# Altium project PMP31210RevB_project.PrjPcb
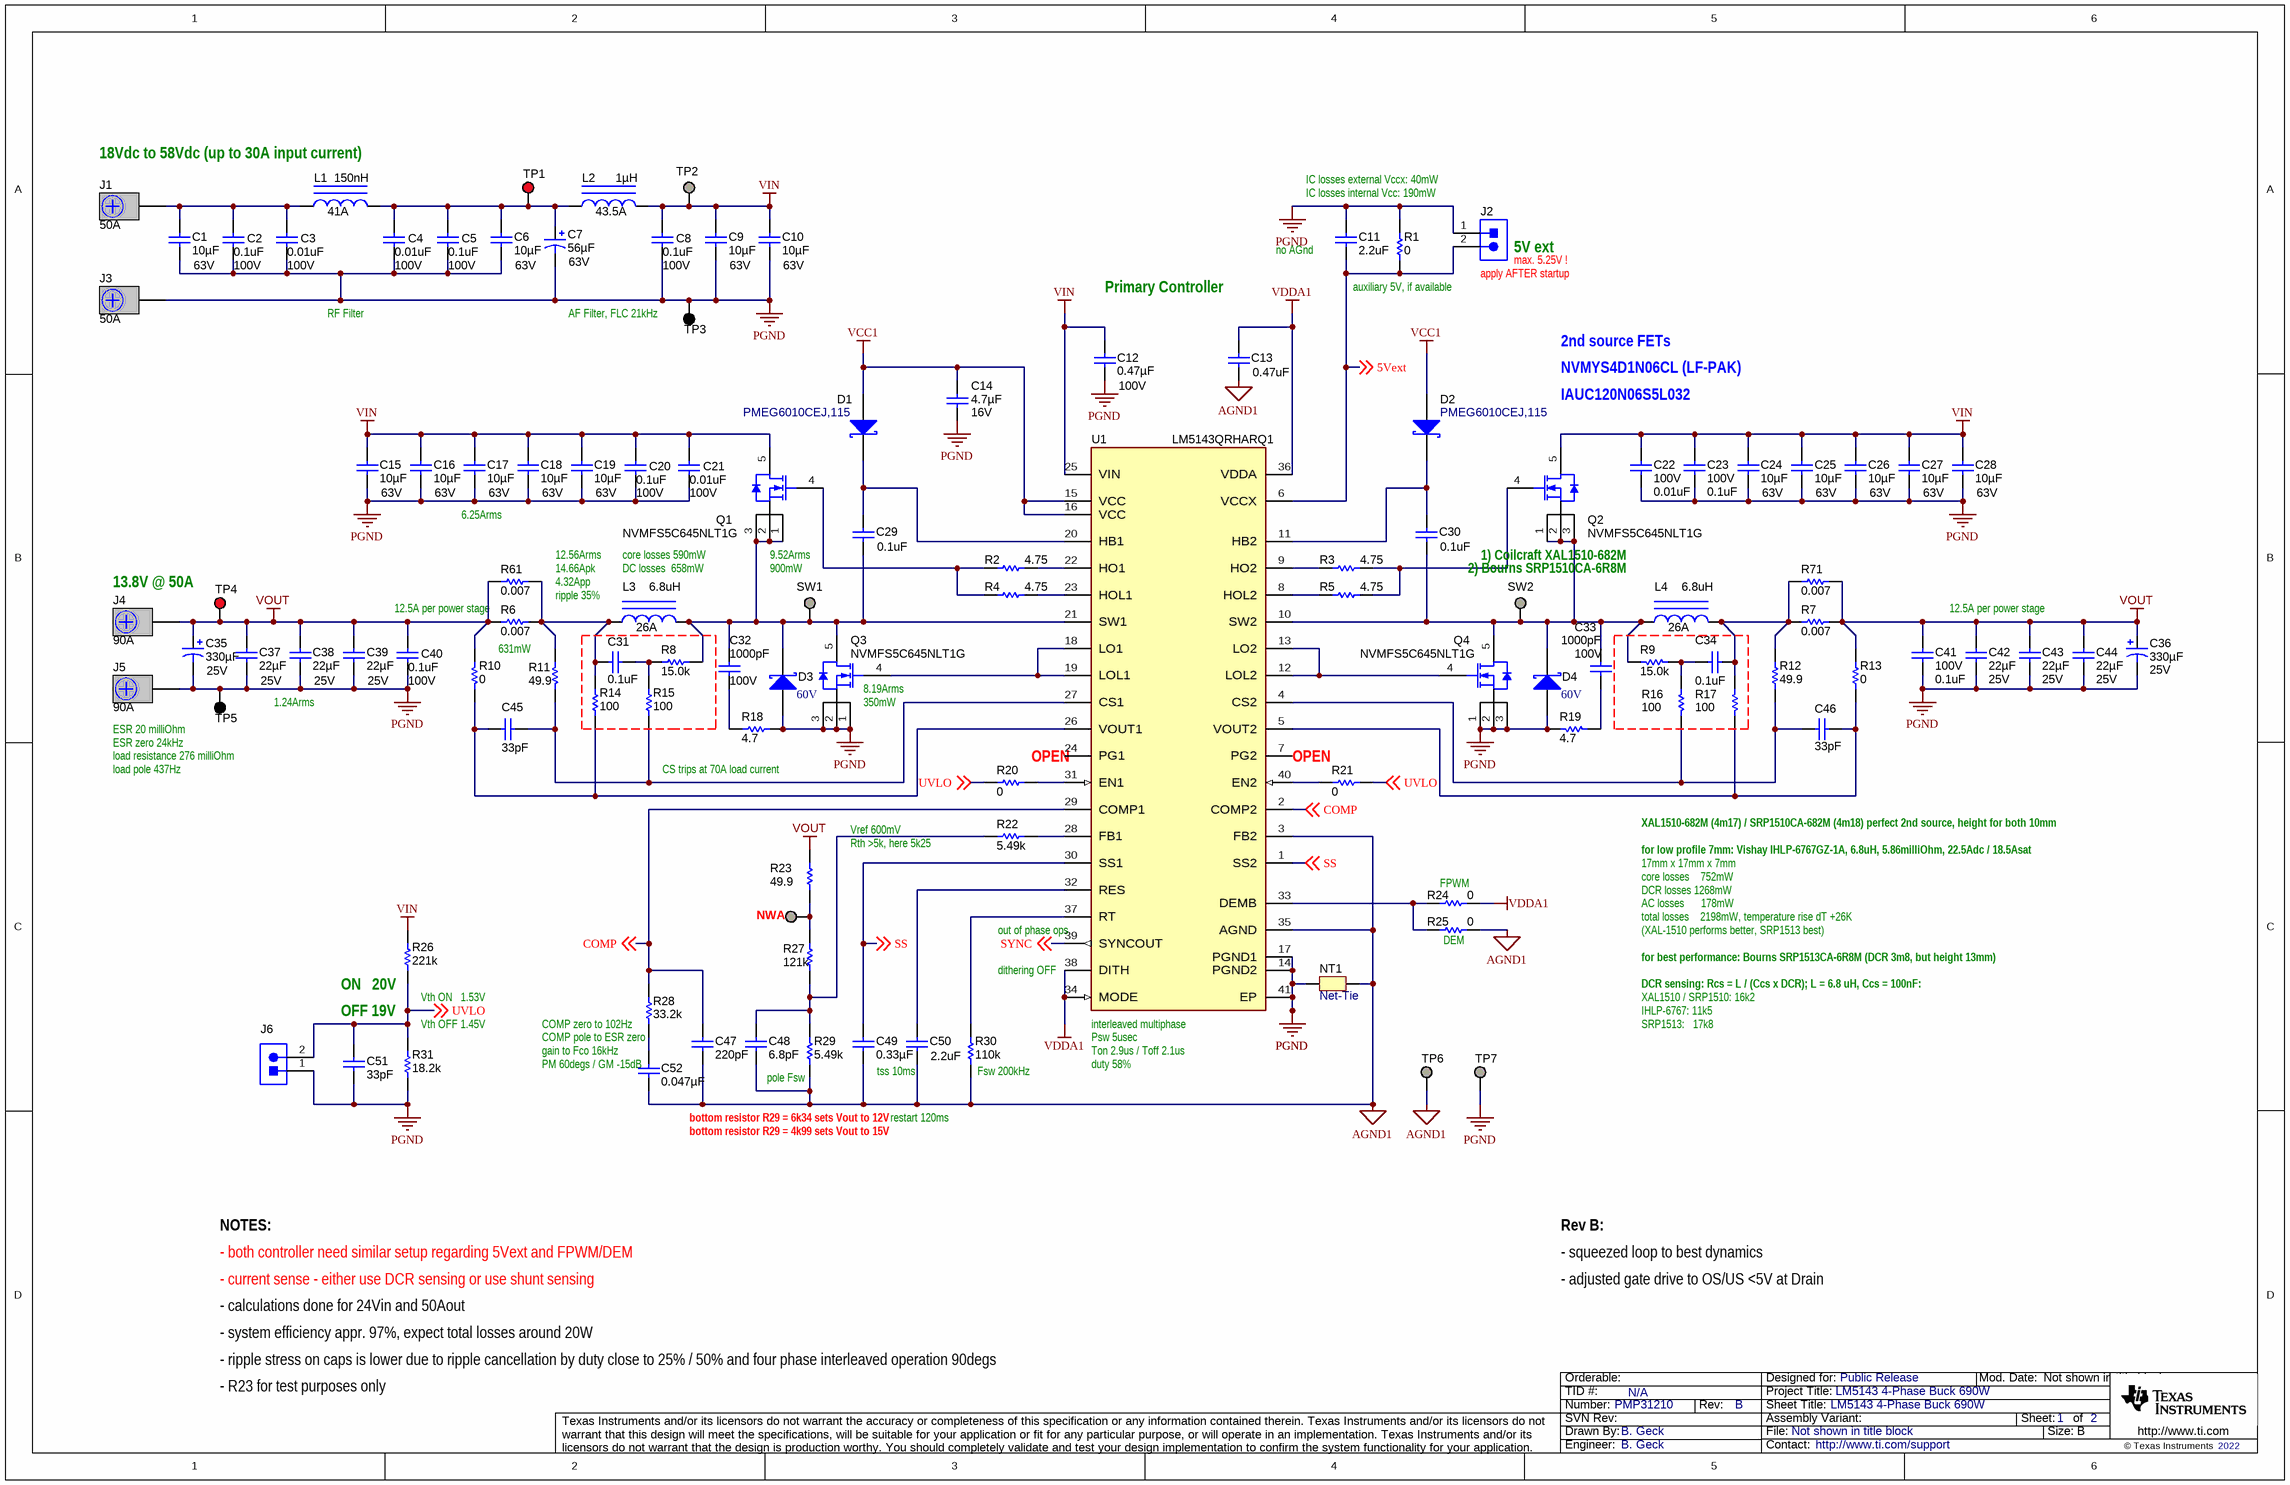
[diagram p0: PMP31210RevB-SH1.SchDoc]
CopyrightYear: 2022; PCB_Layout: B. Geck; PCB_Rev: A3; PRJ_Customer: Public Release; PRJ_Engineer: B. Geck; PRJ_Number: PMP31210; PRJ_Title: LM5143 4-Phase Buck 690W; SCH_Rev: B; TechSupport: http://www.ti.com/support; TID: N/A
2 sheets, 194 parts. Net scope: global (net labels, ports and power ports of the same name join across sheets).
Board file: PMP31202RevA3_board.PcbDoc
Sheets:
  PMP31210RevB-SH1.SchDoc
  PMP31210RevB-SH2.SchDoc

## Sheet PMP31210RevB-SH1.SchDoc: LM5143 4-Phase Buck 690W
size 431 x 279 mm; Date: Not shown in title block; ApprovedBy: Not shown in title block; CheckedBy: Not shown in title block; Author: Not shown in title block; CompanyName: Not shown in title block; DrawnBy: B. Geck; Engineer: Not shown in title block; Organization: Not shown in title block; Address1: Not shown in title block; Address2: Not shown in title block; Address3: Not shown in title block; Address4: Not shown in title block; DocumentNumber: 2; Revision: Use project parameter SCH_Rev; SheetNumber: 1; SheetTotal: 2; PageSetup: Record=PageOptions¦CenterHorizontal=True¦CenterVertical=True¦PrintScale=0.96¦XCorrection=1.00¦YCorrection=1.00¦PrintKind=0¦BorderSize=5000000¦LeftOffset=0¦BottomOffset=0¦Orientation=2¦PaperLength=1000¦PaperWidth=1000¦Scale=100¦PaperSource=7¦PrintQuality=600¦MediaType=1¦DitherType=10¦PaperKind=11" x 17"¦PrintScaleMode=1

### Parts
C1  ValueDisplayed: 10µF  Value2: 63V  [1210_270]  (hidden comment: GRM32ER71J106KA12L)
C2  VDC_V: 100V  ValueDisplayed: 0.1uF  [0805_HV]  (hidden comment: C0805C104K1RACTU)
C3  Value2: 100V  ValueDisplayed: 0.01uF  [0603L]  (hidden comment: GRM188R72A103KA01D)
C4  Value2: 100V  ValueDisplayed: 0.01uF  [0603L]  (hidden comment: GRM188R72A103KA01D)
C5  VDC_V: 100V  ValueDisplayed: 0.1uF  [0805_HV]  (hidden comment: C0805C104K1RACTU)
C6  ValueDisplayed: 10µF  Value2: 63V  [1210_270]  (hidden comment: GRM32ER71J106KA12L)
C7  ValueDisplayed: 56µF  Value2: 63V  [SM_RADIAL_10BMM]  (hidden comment: EEHZC1J560P)
C8  VDC_V: 100V  ValueDisplayed: 0.1uF  [0805_HV]  (hidden comment: C0805C104K1RACTU)
C9  ValueDisplayed: 10µF  Value2: 63V  [1210_270]  (hidden comment: GRM32ER71J106KA12L)
C10  ValueDisplayed: 10µF  Value2: 63V  [1210_270]  (hidden comment: GRM32ER71J106KA12L)
C11  ValueDisplayed: 2.2uF  [0603L]  (hidden comment: GRM188R71A225KE15D)
C12  ValueDisplayed: 0.47µF  Value2: 100V  [0805_HV]  (hidden comment: GRM21BR72A474KA73L)
C13  ValueDisplayed: 0.47uF  [0603L]  (hidden comment: GCM188R71C474KA55D)
C14  ValueDisplayed: 4.7µF  Value2: 16V  [0603]  (hidden comment: GRM188Z71C475KE21D)
C15  ValueDisplayed: 10µF  Value2: 63V  [1210_270]  (hidden comment: GRM32ER71J106KA12L)
C16  ValueDisplayed: 10µF  Value2: 63V  [1210_270]  (hidden comment: GRM32ER71J106KA12L)
C17  ValueDisplayed: 10µF  Value2: 63V  [1210_270]  (hidden comment: GRM32ER71J106KA12L)
C18  ValueDisplayed: 10µF  Value2: 63V  [1210_270]  (hidden comment: GRM32ER71J106KA12L)
C19  ValueDisplayed: 10µF  Value2: 63V  [1210_270]  (hidden comment: GRM32ER71J106KA12L)
C20  VDC_V: 100V  ValueDisplayed: 0.1uF  [0805_HV]  (hidden comment: C0805C104K1RACTU)
C21  Value2: 100V  ValueDisplayed: 0.01uF  [0603L]  (hidden comment: GRM188R72A103KA01D)
C22  Value2: 100V  ValueDisplayed: 0.01uF  [0603L]  (hidden comment: GRM188R72A103KA01D)
C23  VDC_V: 100V  ValueDisplayed: 0.1uF  [0805_HV]  (hidden comment: C0805C104K1RACTU)
C24  ValueDisplayed: 10µF  Value2: 63V  [1210_270]  (hidden comment: GRM32ER71J106KA12L)
C25  ValueDisplayed: 10µF  Value2: 63V  [1210_270]  (hidden comment: GRM32ER71J106KA12L)
C26  ValueDisplayed: 10µF  Value2: 63V  [1210_270]  (hidden comment: GRM32ER71J106KA12L)
C27  ValueDisplayed: 10µF  Value2: 63V  [1210_270]  (hidden comment: GRM32ER71J106KA12L)
C28  ValueDisplayed: 10µF  Value2: 63V  [1210_270]  (hidden comment: GRM32ER71J106KA12L)
C29  ValueDisplayed: 0.1uF  [0603L]  (hidden comment: CGA3E2X7R1E104K080AA)
C30  ValueDisplayed: 0.1uF  [0603L]  (hidden comment: CGA3E2X7R1E104K080AA)
C31  ValueDisplayed: 0.1uF  [0603L]  (hidden comment: CGA3E2X7R1E104K080AA)
C32  ValueDisplayed: 1000pF  Value2: 100V  [0603]  (hidden comment: GRM188R72A102KA01D)
C33  ValueDisplayed: 1000pF  Value2: 100V  [0603]  (hidden comment: GRM188R72A102KA01D)
C34  ValueDisplayed: 0.1uF  [0603L]  (hidden comment: CGA3E2X7R1E104K080AA)
C35  ValueDisplayed: 330µF  Value2: 25V  [SM_RADIAL_10BMM]  (hidden comment: EEHZC1E331P)
C36  ValueDisplayed: 330µF  Value2: 25V  [SM_RADIAL_10BMM]  (hidden comment: EEHZC1E331P)
C37  ValueDisplayed: 22µF  Value2: 25V  [1210_270]  (hidden comment: GRM32ER71E226KE15L)
C38  ValueDisplayed: 22µF  Value2: 25V  [1210_270]  (hidden comment: GRM32ER71E226KE15L)
C39  ValueDisplayed: 22µF  Value2: 25V  [1210_270]  (hidden comment: GRM32ER71E226KE15L)
C40  VDC_V: 100V  ValueDisplayed: 0.1uF  [0805_HV]  (hidden comment: C0805C104K1RACTU)
C41  VDC_V: 100V  ValueDisplayed: 0.1uF  [0805_HV]  (hidden comment: C0805C104K1RACTU)
C42  ValueDisplayed: 22µF  Value2: 25V  [1210_270]  (hidden comment: GRM32ER71E226KE15L)
C43  ValueDisplayed: 22µF  Value2: 25V  [1210_270]  (hidden comment: GRM32ER71E226KE15L)
C44  ValueDisplayed: 22µF  Value2: 25V  [1210_270]  (hidden comment: GRM32ER71E226KE15L)
C45  ValueDisplayed: 33pF  [0603L]  (hidden comment: 06031A330JAT2A)
C46  ValueDisplayed: 33pF  [0603L]  (hidden comment: 06031A330JAT2A)
C47  ValueDisplayed: 220pF  [0603]  (hidden comment: GRM188R71H221KA01D)
C48  ValueDisplayed: 6.8pF  [0603]  (hidden comment: 06035A6R8CAT2A)
C49  ValueDisplayed: 0.33µF  [0603]  (hidden comment: GRM188R71C334KA01D)
C50  ValueDisplayed: 2.2uF  [0603L]  (hidden comment: GRM188R71A225KE15D)
C51  ValueDisplayed: 33pF  [0603L]  (hidden comment: 06031A330JAT2A)
C52  ValueDisplayed: 0.047µF  [0603]  (hidden comment: GRM188R71C473KA01D)
D1  PMEG6010CEJ,115  [SOD-323F]
D2  PMEG6010CEJ,115  [SOD-323F]
D3  value 60V  [SMA]  (hidden comment: B360A-13-F)
D4  value 60V  [SMA]  (hidden comment: B360A-13-F)
J1  Current_A: 50A  [CB35-36-CY]  (hidden comment: CB35-36-CY)
J2  TSM-102-03-T-SV  [Samtec_TSM-102-03-x-SV]  (value not drawn)
J3  Current_A: 50A  [CB35-36-CY]  (hidden comment: CB35-36-CY)
J4  Current_A: 90A  [CB70-14-CY]  (hidden comment: CB70-14-CY)
J5  Current_A: 90A  [CB70-14-CY]  (hidden comment: CB70-14-CY)
J6  TSM-102-03-T-SV  [Samtec_TSM-102-03-x-SV]  (value not drawn)
L1  ValueDisplayed: 150nH  Value2: 41A  [PA2607NL]  (hidden comment: PA2607.151NLT)
L2  ValueDisplayed: 1µH  Value2: 43.5A  [XAL1010]  (hidden comment: XAL1010-102MEB)
L3  Imax_A: 26A  ValueDisplayed: 6.8uH  [XAL1510]  (hidden comment: XAL1510-682MEB)
L4  Imax_A: 26A  ValueDisplayed: 6.8uH  [XAL1510]  (hidden comment: XAL1510-682MEB)
NT1  Net-Tie  [Net-Tie_10mil]  (net tie, no BOM)
NWA  5019  [Keystone_5019]  (value not drawn)
Q1  NVMFS5C645NLT1G  [SO-8FL]
Q2  NVMFS5C645NLT1G  [SO-8FL]
Q3  NVMFS5C645NLT1G  [SO-8FL]
Q4  NVMFS5C645NLT1G  [SO-8FL]
R1  ValueDisplayed: 0  [0603]  (hidden comment: CRCW06030000Z0EA)
R2  ValueDisplayed: 4.75  [0603]  (hidden comment: CRCW06034R75FKEA)
R3  ValueDisplayed: 4.75  [0603]  (hidden comment: CRCW06034R75FKEA)
R4  ValueDisplayed: 4.75  [0603]  (hidden comment: CRCW06034R75FKEA)
R5  ValueDisplayed: 4.75  [0603]  (hidden comment: CRCW06034R75FKEA)
R6  ValueDisplayed: 0.007  [PE1206]  (hidden comment: PE1206FRF470R007L)
R7  ValueDisplayed: 0.007  [PE1206]  (hidden comment: PE1206FRF470R007L)
R8  ValueDisplayed: 15.0k  [0603]  (hidden comment: CRCW060315K0FKEA)
R9  ValueDisplayed: 15.0k  [0603]  (hidden comment: CRCW060315K0FKEA)
R10  ValueDisplayed: 0  [0603L]  (hidden comment: CRCW06030000Z0EA)
R11  ValueDisplayed: 49.9  [0603L]  (hidden comment: CRCW060349R9FKEA)
R12  ValueDisplayed: 49.9  [0603L]  (hidden comment: CRCW060349R9FKEA)
R13  ValueDisplayed: 0  [0603L]  (hidden comment: CRCW06030000Z0EA)
R14  ValueDisplayed: 100  [0603]  (hidden comment: CRCW0603100RFKEA)
R15  ValueDisplayed: 100  [0603]  (hidden comment: CRCW0603100RFKEA)
R16  ValueDisplayed: 100  [0603]  (hidden comment: CRCW0603100RFKEA)
R17  ValueDisplayed: 100  [0603]  (hidden comment: CRCW0603100RFKEA)
R18  ValueDisplayed: 4.7  [1206]  (hidden comment: CRCW12064R70JNEAHP)
R19  ValueDisplayed: 4.7  [1206]  (hidden comment: CRCW12064R70JNEAHP)
R20  ValueDisplayed: 0  [0603]  (hidden comment: CRCW06030000Z0EA)
R21  ValueDisplayed: 0  [0603]  (hidden comment: CRCW06030000Z0EA)
R22  ValueDisplayed: 5.49k  [0603]  (hidden comment: CRCW06035K49FKEA)
R23  ValueDisplayed: 49.9  [0603]  (hidden comment: CRCW060349R9FKEA)
R24  ValueDisplayed: 0  [0603]  (hidden comment: CRCW06030000Z0EA)
R25  ValueDisplayed: 0  [0603]  (hidden comment: CRCW06030000Z0EA)
R26  ValueDisplayed: 221k  [0603]  (hidden comment: CRCW0603221KFKEA)
R27  ValueDisplayed: 121k  [0603]  (hidden comment: CRCW0603121KFKEA)
R28  ValueDisplayed: 33.2k  [0603]  (hidden comment: CRCW060333K2FKEA)
R29  ValueDisplayed: 5.49k  [0603]  (hidden comment: CRCW06035K49FKEA)
R30  ValueDisplayed: 110k  [0603]  (hidden comment: CRCW0603110KFKEA)
R31  ValueDisplayed: 18.2k  [0603]  (hidden comment: CRCW060318K2FKEA)
R61  ValueDisplayed: 0.007  [PE1206]  (hidden comment: PE1206FRF470R007L)
R71  ValueDisplayed: 0.007  [PE1206]  (hidden comment: PE1206FRF470R007L)
SW1  5019  [Keystone_5019]  (value not drawn)
SW2  5019  [Keystone_5019]  (value not drawn)
TP1  5010  [Keystone5010]  (value not drawn)
TP2  5019  [Keystone_5019]  (value not drawn)
TP3  5011  [Keystone5011]  (value not drawn)
TP4  5010  [Keystone5010]  (value not drawn)
TP5  5011  [Keystone5011]  (value not drawn)
TP6  5019  [Keystone_5019]  (value not drawn)
TP7  5019  [Keystone_5019]  (value not drawn)
U1  LM5143QRHARQ1  [RHA0040N-MFG]

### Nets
AGND1: C13.1 C47.2 C48.2 C49.2 C50.2 C52.2 NT1.2 R25.2 R29.1 R30.1 TP6.1 U1.3(FB2) U1.35(AGND)
PGND: C1.2 C2.1 C3.1 C4.1 C5.1 C6.2 C7.2(-) C8.1 C9.2 C10.2 C11.2 C12.2 C14.2 C15.2 C16.2 C17.2 C18.2 C19.2 C20.1 C21.1 C22.1 C23.1 C24.2 C25.2 C26.2 C27.2 C28.2 C35.2(-) C36.2(-) C37.2 C38.2 C39.2 C40.1 C41.1 C42.2 C43.2 C44.2 C51.2 D3.2(A) D4.2(A) J2.1 J3.1 J5.1 J6.1 NT1.1 Q3.1(S) Q3.2(S) Q3.3(S) Q4.1(S) Q4.2(S) Q4.3(S) R1.1 R18.1 R19.2 R31.1 TP3.1 TP5.1 TP7.1 U1.14(PGND2) U1.17(PGND1) U1.41(EP)
VCC1: C14.1 D1.2(A) D2.2(A) U1.15(VCC) U1.16(VCC)
VDDA1: C13.2 R24.2 U1.34(MODE) U1.36(VDDA) U1.38(DITH)
VIN: C8.2 C9.1 C10.1 C12.1 C15.1 C16.1 C17.1 C18.1 C19.1 C20.2 C21.2 C22.2 C23.2 C24.1 C25.1 C26.1 C27.1 C28.1 L2.2 Q1.5(D) Q2.5(D) R26.2 TP2.1 U1.25(VIN)
VOUT: C35.1(+) C36.1(+) C37.1 C38.1 C39.1 C40.2 C41.2 C42.1 C43.1 C44.1 J4.1 R6.1 R7.2 R10.2 R13.2 R23.2 R61.1 R71.2 TP4.1
5Vext: C11.1 J2.2 R1.2 U1.6(VCCX) ; off-sheet 5Vext
COMP: C47.1 R28.2 U1.2(COMP2) U1.29(COMP1) ; off-sheet COMP
SS: C49.1 U1.1(SS2) U1.30(SS1) ; off-sheet SS
SYNC: U1.39(SYNCOUT) ; off-sheet SYNC
UVLO: C51.1 J6.2 R20.1 R21.2 R26.1 R31.2 ; off-sheet UVLO
NetC1_1: C1.1 C2.2 C3.2 J1.1 L1.1
NetC4_2: C4.2 C5.2 C6.1 C7.1(+) L1.2 L2.1 TP1.1
NetC29_1: C29.1 C32.1 D3.1(K) L3.2 Q1.1(S) Q1.2(S) Q1.3(S) Q3.5(D) R8.2 SW1.1 U1.21(SW1)
NetC29_2: C29.2 D1.1(K) U1.20(HB1)
NetC30_1: C30.1 C33.1 D4.1(K) L4.2 Q2.1(S) Q2.2(S) Q2.3(S) Q4.5(D) R9.2 SW2.1 U1.10(SW2)
NetC30_2: C30.2 D2.1(K) U1.11(HB2)
NetC31_1: C31.1 R8.1 R15.2
NetC31_2: C31.2 L3.1 R6.2 R11.2 R14.2 R61.2
NetC32_2: C32.2 R18.2
NetC33_2: C33.2 R19.1
NetC34_1: C34.1 R9.1 R16.2
NetC34_2: C34.2 L4.1 R7.1 R12.2 R17.2 R71.1
NetC45_1: C45.1 R10.1 R14.1 U1.26(VOUT1)
NetC45_2: C45.2 R11.1 R15.1 U1.27(CS1)
NetC46_1: C46.1 R13.1 R17.1 U1.5(VOUT2)
NetC46_2: C46.2 R12.1 R16.1 U1.4(CS2)
NetC48_1: C48.1 R22.1 R27.1 R29.2
NetC50_1: C50.1 U1.32(RES)
NetC52_1: C52.1 R28.1
NetNWA_1: NWA.1 R23.1 R27.2
NetQ1_4: Q1.4(G) R2.1 R4.1
NetQ2_4: Q2.4(G) R3.2 R5.2
NetQ3_4: Q3.4(G) U1.18(LO1) U1.19(LOL1)
NetQ4_4: Q4.4(G) U1.12(LOL2) U1.13(LO2)
NetR2_2: R2.2 U1.22(HO1)
NetR3_1: R3.1 U1.9(HO2)
NetR4_2: R4.2 U1.23(HOL1)
NetR5_1: R5.1 U1.8(HOL2)
NetR20_2: R20.2 U1.31(EN1)
NetR21_1: R21.1 U1.40(EN2)
NetR22_2: R22.2 U1.28(FB1)
NetR24_1: R24.1 R25.1 U1.33(DEMB)
NetR30_2: R30.2 U1.37(RT)

Not connected (* = marked no-connect by the designer): U1 7(PG2) 24(PG1)

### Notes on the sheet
- 18Vdc to 58Vdc (up to 30A input current)
- IC losses external Vccx: 40mW
- IC losses internal Vcc: 190mW
- Primary Controller
- (near C11) no AGnd
- auxiliary 5V, if available
- (near J2) apply AFTER startup
- (near J2) 5V ext
- (near J2) max. 5.25V !
- RF Filter
- (near TP3) AF Filter, FLC 21kHz
- 2nd source FETs
- NVMYS4D1N06CL (LF-PAK)
- IAUC120N06S5L032
- 6.25Arms
- (near R61) 12.56Arms
- (near R61) 14.66Apk
- core losses 590mW
- DC losses  658mW
- 9.52Arms
- 900mW
- (near R71) 1) Coilcraft XAL1510-682M
- (near R71) 2) Bourns SRP1510CA-6R8M
- 13.8V @ 50A
- (near R6) 12.5A per power stage
- 4.32App
- ripple 35%
- (near R7) 12.5A per power stage
- 1.24Arms
- 631mW
- (near Q3) 8.19Arms
- (near Q3) 350mW
- load resistance 276 milliOhm
- ESR 20 milliOhm
- ESR zero 24kHz
- load pole 437Hz
- CS trips at 70A load current
- OPEN
- (near R23) Vref 600mV
- Rth >5k, here 5k25
- XAL1510-682M (4m17) / SRP1510CA-682M (4m18) perfect 2nd source, height for both 10mm
- (near R24) FPWM
- for low profile 7mm: Vishay IHLP-6767GZ-1A, 6.8uH, 5.86milliOhm, 22.5Adc / 18.5Asat
- 17mm x 17mm x 7mm
- core losses    752mW
- DCR losses 1268mW
- AC losses      178mW
- (near U1) dithering OFF
- (near U1) out of phase ops
- (near R25) DEM
- total losses    2198mW, temperature rise dT +26K
- (XAL-1510 performs better, SRP1513 best)
- for best performance: Bourns SRP1513CA-6R8M (DCR 3m8, but height 13mm)
- (near R26) ON   20V
- OFF 19V
- (near R26) Vth ON   1.53V
- (near R31) Vth OFF 1.45V
- (near R28) COMP zero to 102Hz
- (near R28) COMP pole to ESR zero
- (near U1) interleaved multiphase
- (near U1) Psw 5usec
- DCR sensing: Rcs = L / (Ccs x DCR); L = 6.8 uH, Ccs = 100nF:
- XAL1510 / SRP1510: 16k2
- IHLP-6767: 11k5
- SRP1513:   17k8
- (near C52) gain to Fco 16kHz
- (near C52) PM 60degs / GM -15dB
- (near R29) pole Fsw
- tss 10ms
- (near R30) Fsw 200kHz
- (near U1) Ton 2.9us / Toff 2.1us
- duty 58%
- bottom resistor R29 = 6k34 sets Vout to 12V
- bottom resistor R29 = 4k99 sets Vout to 15V
- restart 120ms
- NOTES:
- Rev B:
- - calculations done for 24Vin and 50Aout
- - both controller need similar setup regarding 5Vext and FPWM/DEM
- - current sense - either use DCR sensing or use shunt sensing
- - squeezed loop to best dynamics
- - adjusted gate drive to OS/US <5V at Drain
- - ripple stress on caps is lower due to ripple cancellation by duty close to 25% / 50% and four phase interleaved operation 90degs
- - system efficiency appr. 97%, expect total losses around 20W
- - R23 for test purposes only

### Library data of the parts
C1 C6 C9 C10 C15-C19 C24-C28 = GRM32ER71J106KA12L: CAP, CERM, 10 µF, 63 V,+/- 10%, X7R, 1210; Manufacturer: MuRata; Polarized: N; CompType: Capacitor; Value: 10uF; U/M: EA; Cap_F: 0.00001; Tolerance_%: 10; VDC_V: 63; TaMin_C: -55; TaMax_C: 125; Cap_Case: 1210; SizeArea_mm2: 8; SizeAreaWB_mm2: 14.7; SizeX_mm: 3.2; SizeY_mm: 2.5; SizeZ_mm: 2.7; AEC Category: Q200; Green_Lifecycle: Active; Green_REACh: Passed
C2 C5 C8 C20 C23 C40 C41 = CMP-0007722-2: CAP, CERM, 0.1 uF, 100 V, +/- 10%, X7R, 0805; Manufacturer: Kemet; TaMin_C: -55°C; ESR_ohm: 0.064; Polarized: N; SizeAreaWB_mm2: 6.75; Value1: 0.064 ohm; U/M: EA; Value: 0.1uF; TaMax_C: 125°C; SizeZ_mm: 1.45; SizeX_mm: 2; SizeY_mm: 1.25; Cap_Case: 0805; SizeArea_mm2: 2.5; CompType: Capacitor; Cap_F: 100nF; IRMS_A: 1.64A; AEC Category: Q200
C3 C4 C21 C22 = CMP-0007468-5: CAP, CERM, 0.01 uF, 100 V, +/- 10%, X7R, 0603; Manufacturer: MuRata; TaMin_C: -55°C; Polarized: N; SizeAreaWB_mm2: 4.68; Value1: Unknown; U/M: EA; Value: 0.01uF; TaMax_C: 125°C; SizeZ_mm: 1; SizeX_mm: 1.6; SizeY_mm: 0.8; Cap_Case: 0603; SizeArea_mm2: 1.28; Cap_F: 10nF; AEC Category: Q200
C7 = EEHZC1J560P: CAP, Polymer Hybrid, 56 µF, 63 V,+/- 20%, 30 ohm, 10x10 SMD; Manufacturer: Panasonic; Polarized: Y; CompType: Capacitor; Value: 56uF; U/M: EA; Cap_F: 0.000056; Tolerance_%: 20; Value1: 30 ohm; VDC_V: 63; ESR_ohm: 30; IRMS_A: 1.4; TaMin_C: -55; TaMax_C: 125; SizeAreaWB_mm2: 159.9; SizeArea_mm2: 113.3; SizeX_mm: 11; SizeY_mm: 10.3; SizeZ_mm: 10.2; AEC Category: Q200
C11 = CMP-0007370-4: CAP, CERM, 2.2 uF, 10 V, +/- 10%, X7R, 0603; Manufacturer: MuRata; TaMin_C: -55°C; Polarized: N; SizeAreaWB_mm2: 4.68; Value1: 0.009 ohm; U/M: EA; Value: 2.2uF; TaMax_C: 125°C; SizeZ_mm: 1; SizeX_mm: 1.6; SizeY_mm: 0.8; Cap_Case: 0603; Value2: 10V; SizeArea_mm2: 1.28; CompType: Capacitor; Cap_F: 2.2µF; AEC Category: Q200; ESR_ohm: 9m
C12 = GRM21BR72A474KA73L: CAP, CERM, 0.47 µF, 100 V,+/- 10%, X7R, 0805; Manufacturer: MuRata; Polarized: N; CompType: Capacitor; Value: 0.47uF; U/M: EA; Cap_F: 0.00000047; Tolerance_%: 10; VDC_V: 100; TaMin_C: -55; TaMax_C: 125; Cap_Case: 0805; SizeArea_mm2: 2.5; SizeAreaWB_mm2: 6.75; SizeX_mm: 2; SizeY_mm: 1.25; SizeZ_mm: 1.45; AEC Category: Q200; Green_Lifecycle: Active; Green_REACh: Passed
C13 = CMP-0007138-4: CAP, CERM, 0.47 uF, 16 V, +/- 10%, X7R, AEC-Q200 Grade 1, 0603; Manufacturer: MuRata; TaMin_C: -55°C; Polarized: N; SizeAreaWB_mm2: 4.68; Value1: Unknown; U/M: EA; Value: 0.47uF; TaMax_C: 125°C; SizeZ_mm: 1; SizeX_mm: 1.6; SizeY_mm: 0.8; Cap_Case: 0603; Value2: 16V; SizeArea_mm2: 1.28; CompType: Capacitor; AEC Qualified: Y; Cap_F: 470nF; AEC Category: Q200
C14 = GRM188Z71C475KE21D: CAP, CERM, 4.7 µF, 16 V,+/- 10%, X7R, 0603; Manufacturer: MuRata; Polarized: N; CompType: Capacitor; Value: 4.7uF; U/M: EA; Cap_F: 0.0000047; Tolerance_%: 10; VDC_V: 16; TaMin_C: -55; TaMax_C: 125; SizeArea_mm2: 1.28; SizeAreaWB_mm2: 4.68; SizeX_mm: 1.6; SizeY_mm: 0.8; SizeZ_mm: 1; AEC Category: Q200
C29-C31 C34 = CMP-0007077-5: CAP, CERM, 0.1 uF, 25 V, +/- 10%, X7R, AEC-Q200 Grade 1, 0603; Manufacturer: TDK; TaMin_C: -55°C; Polarized: N; SizeAreaWB_mm2: 4.68; Value1: Unknown; U/M: EA; Value: 0.1uF; TaMax_C: 125°C; SizeZ_mm: 1; SizeX_mm: 1.6; SizeY_mm: 0.8; Cap_Case: 0603; Value2: 25V; SizeArea_mm2: 1.28; AEC Qualified: Y; Cap_F: 100nF; AEC Category: Q200
C32 C33 = GRM188R72A102KA01D: CAP, CERM, 1000 pF, 100 V,+/- 10%, X7R, 0603; Manufacturer: MuRata; Polarized: N; CompType: Capacitor; Value: 1000pF; U/M: EA; Cap_F: 0.000000001; Tolerance_%: 10; VDC_V: 100; TaMin_C: -55; TaMax_C: 125; SizeArea_mm2: 1.28; SizeAreaWB_mm2: 4.68; SizeX_mm: 1.6; SizeY_mm: 0.8; SizeZ_mm: 1; AEC Category: Q200; Green_Lifecycle: Active; Green_REACh: Passed
C35 C36 = EEHZC1E331P: CAP, Polymer Hybrid, 330 µF, 25 V,+/- 20%, 20 ohm, 10x10 SMD; Manufacturer: Panasonic; Polarized: Y; CompType: Capacitor; Value: 330uF; U/M: EA; Cap_F: 0.00033; Tolerance_%: 20; Value1: 20 ohm; VDC_V: 25; IRMS_A: 2; TaMin_C: -55; TaMax_C: 125; SizeAreaWB_mm2: 159.9; SizeArea_mm2: 113.3; SizeX_mm: 11; SizeY_mm: 10.3; SizeZ_mm: 10.2; AEC Category: Q200
C37-C39 C42-C44 = GRM32ER71E226KE15L: CAP, CERM, 22 µF, 25 V,+/- 10%, X7R, 1210; Manufacturer: MuRata; Polarized: N; CompType: Capacitor; Value: 22uF; U/M: EA; Cap_F: 0.000022; Tolerance_%: 10; ESR_ohm: 0.002334; Value1: 0.002334 ohm; VDC_V: 25; IRMS_A: 3.832999; TaMin_C: -55; TaMax_C: 125; Cap_Case: 1210; SizeArea_mm2: 8; SizeAreaWB_mm2: 14.7; SizeX_mm: 3.2; SizeY_mm: 2.5; SizeZ_mm: 2.7; AEC Category: Q200; Green_Lifecycle: Active; Green_REACh: Passed
C45 C46 C51 = CMP-0006722-4: CAP, CERM, 33 pF, 100 V, +/- 5%, C0G/NP0, 0603; Manufacturer: AVX; TaMin_C: -55°C; ESR_ohm: 2.09d; Polarized: N; SizeAreaWB_mm2: 4.68; Value1: 0.209 ohm; U/M: EA; Value: 33pF; TaMax_C: 125°C; SizeZ_mm: 1; SizeX_mm: 1.6; SizeY_mm: 0.8; Cap_Case: 0603; Value2: 100V; SizeArea_mm2: 1.28; CompType: Capacitor; AEC Category: Q200
C47 = GRM188R71H221KA01D: CAP, CERM, 220 pF, 50 V,+/- 10%, X7R, 0603; Manufacturer: MuRata; Polarized: N; CompType: Capacitor; Value: 220pF; U/M: EA; Cap_F: 0.00000000022; Tolerance_%: 10; VDC_V: 50; Value2: 50V; TaMin_C: -55; TaMax_C: 125; SizeArea_mm2: 1.28; SizeAreaWB_mm2: 4.68; SizeX_mm: 1.6; SizeY_mm: 0.8; SizeZ_mm: 1; AEC Category: Q200; Green_Lifecycle: Active; Green_REACh: Passed
C48 = 06035A6R8CAT2A: CAP, CERM, 6.8 pF, 50 V,+/- 4%, C0G/NP0, 0603; Manufacturer: AVX; Polarized: N; CompType: Capacitor; Value: 6.8pF; U/M: EA; Cap_F: 0.0000000000068; Tolerance_%: 4; ESR_ohm: 0.505; Value1: 0.505 ohm; VDC_V: 50; Value2: 50V; TaMin_C: -55; TaMax_C: 125; SizeArea_mm2: 1.28; SizeAreaWB_mm2: 4.68; SizeX_mm: 1.6; SizeY_mm: 0.8; SizeZ_mm: 1; AEC Category: Q200; Green_Lifecycle: Active; Green_REACh: Passed
C49 = GRM188R71C334KA01D: CAP, CERM, 0.33 µF, 16 V,+/- 10%, X7R, 0603; Manufacturer: MuRata; Polarized: N; CompType: Capacitor; Value: 0.33uF; U/M: EA; Cap_F: 0.00000033; Tolerance_%: 10; VDC_V: 16; Value2: 16V; TaMin_C: -55; TaMax_C: 125; SizeArea_mm2: 1.28; SizeAreaWB_mm2: 4.68; SizeX_mm: 1.6; SizeY_mm: 0.8; SizeZ_mm: 1; AEC Category: Q200; Green_Lifecycle: Active; Green_REACh: Passed
C50 = CMP-0007370-4: CAP, CERM, 2.2 uF, 10 V, +/- 10%, X7R, 0603; Manufacturer: MuRata; TaMin_C: -55°C; ESR_ohm: 9m; Polarized: N; SizeAreaWB_mm2: 4.68; Value1: 0.009 ohm; U/M: EA; Value: 2.2uF; TaMax_C: 125°C; SizeZ_mm: 1; SizeX_mm: 1.6; SizeY_mm: 0.8; Cap_Case: 0603; Value2: 10V; SizeArea_mm2: 1.28; CompType: Capacitor; Cap_F: 2.2µF; AEC Category: Q200
C52 = GRM188R71C473KA01D: CAP, CERM, 0.047 µF, 16 V,+/- 10%, X7R, 0603; Manufacturer: MuRata; Polarized: N; CompType: Capacitor; Value: 0.047uF; U/M: EA; Cap_F: 0.000000047; Tolerance_%: 10; VDC_V: 16; Value2: 16V; TaMin_C: -55; TaMax_C: 125; SizeArea_mm2: 1.28; SizeAreaWB_mm2: 4.68; SizeX_mm: 1.6; SizeY_mm: 0.8; SizeZ_mm: 1; AEC Category: Q200; Green_Lifecycle: Active; Green_REACh: Passed
D1 D2 = CMP-0077011-2: Diode, Schottky, 60 V, 1 A, SOD-323F; Manufacturer: Nexperia; SizeAreaWB_mm2: 7.875; Vr_V: 60V; SizeArea_mm2: 3.125; TJmax_C: 150°C; AEC Category: Q101; Value: 60V; SizeZ_mm: 0.8; Green_REACh: Incomplete; Io_A: 1A; Vf_V: 660mV; SizeY_mm: 1.25; Value2: 0.66V; Green_Lifecycle: Not Set; SizeX_mm: 2.5
D3 D4 = B360A-13-F: Diode, Schottky, 60 V, 3 A, SMA; Manufacturer: Diodes Inc.; U/M: EA; Vf_V: 0.7; Value1: 3A; Value2: 0.7V; Io_A: 3; Vr_V: 60; TJmax_C: 125; RJC_CperW: 25; SizeAreaWB_mm2: 37.3428; SizeArea_mm2: 16.3228; SizeX_mm: 5.59; SizeY_mm: 2.92; SizeZ_mm: 2.87; AEC Category: Q101; Green_Lifecycle: Active; Green_REACh: Passed
J1 J3 = CB35-36-CY: Terminal 50A Lug; Manufacturer: Panduit; SymbolCreator: crossc; CompType: Screw Terminal; ContactFinish: Copper; Voltage_V: 600; Cert_CULUS: Y; Green_Lifecycle: Not Set; Green_REACh: Incomplete
J2 J6 = TSM-102-03-T-SV: Header, 2.54mm, 2x1, Tin, SMT; Manufacturer: Samtec; SymbolCreator: a0412235; Pitch_mm: 2.54; Gender: Male; Shrouded: N; Row_Count: 1; Current_A: 5.4; Voltage_V: 475; Cert_CSA: Y; Green_Lifecycle: Active; Green_REACh: Passed
J4 J5 = CB70-14-CY: Terminal 90A Lug; Manufacturer: Panduit; SymbolCreator: crossc; CompType: Screw Terminal; ContactFinish: Copper; Voltage_V: 600; Cert_CULUS: Y; Green_Lifecycle: Not Set; Green_REACh: Incomplete
L1 = PA2607.151NLT: Inductor, Ferrite Bead, Ferrite, 150 nH, 41 A, 0.00029 ohm, SMD; Manufacturer: Pulse Engineering; Value: 150nH; Ind_H: 150.0E-9; Imax_A: 41; Irms: 41A @ 40C rise; Isat: 72A @ 20% inductance drop; SizeAreaWB_mm2: 118.7915; SizeArea_mm2: 78.8715; SizeX_mm: 7.65; SizeY_mm: 10.31; SizeZ_mm: 7.4; AEC Category: Q200
L2 = XAL1010-102MEB: Inductor, Shielded, Composite, 1 µH, 43.5 A, 0.001 ohm, SMD; Manufacturer: Coilcraft; Value: 1uH; Ind_H: 1.0E-6; Imax_A: 43.5; Irms: 43.5A @ 40C rise; Isat: 55A @ 30% inductance drop; DCR_ohm: 0.001; SizeAreaWB_mm2: 159.6; SizeArea_mm2: 113; SizeX_mm: 11.3; SizeY_mm: 10; AEC Category: Q200; Green_Lifecycle: Not Set; Green_REACh: Incomplete
L3 L4 = CMP-0060971-1: Inductor, Shielded, Composite, 6.8 uH, 26 A, 0.00417 ohm, SMD; Manufacturer: Coilcraft; Isat: 36A @ 30% inductance drop; Irms: 26A @ 40C rise; SizeAreaWB_mm2: 320.16; DCR_ohm: 4.17m; Value: 6.8uH; SizeZ_mm: 10; SizeX_mm: 16.4; SizeY_mm: 15.4; SizeArea_mm2: 252.56; Ind_H: 6.8µH; AEC Category: Q200
NT1 = CMP-0078142-3: Single point connection between nets.
NWA SW1 SW2 TP2 TP6 TP7 = CMP-0055162-1: Test Point, Miniature, SMT; Manufacturer: Keystone; CNHeader: FALSE; Green_Lifecycle: Active; Green_REACh: Passed; CT: TRUE
Q1-Q4 = NVMFS5C682NLT1G: MOSFET, N-CH, 60 V, 40 A, AEC-Q101, SO-8FL; Manufacturer: ON Semiconductor; Alternate Manufacturer: None; U/M: EA; ChType: N; Value: 60V; VdsMax_V: 60; Value1: 0.004 ohm; Rdson45_ohm: 0.004; Value2: 34 nC; QgTyp_nC: 34; Vgs_V: 20; IdsMax_A: 40; SizeAreaWB_mm2: 58.2725; SizeArea_mm2: 31.6725; SizeX_mm: 6.15; SizeY_mm: 5.15; SizeZ_mm: 1.1; AEC Category: Q101; AEC Qualified: Y
R1 R20 R21 R24 R25 = CRCW06030000Z0EA: RES, 0, 5%, 0.1 W, 0603; Manufacturer: Vishay-Dale; CompType: Resistor; Value: 0; Value_Code: 0000; Tolerance_%: 5; Power_W: 0.1; Value2: 0.1W; VDC_V: 75; TempCo: 200 ppm/C; SizeArea_mm2: 1.28; SizeX_mm: 1.6; SizeY_mm: 0.8; SizeZ_mm: 1; EIA_Code: E24; U/M: EA; AEC Category: Q200; Green_Lifecycle: Active; Green_REACh: Passed
R2-R5 = CRCW06034R75FKEA: RES, 4.75, 1%, 0.1 W, 0603; Manufacturer: Vishay-Dale; CompType: Resistor; Value: 4.75; Value_Code: 4R75; Tolerance_%: 1; Power_W: 0.1; Value2: 0.1W; VDC_V: 75; TempCo: 100 ppm/C; SizeArea_mm2: 1.28; SizeX_mm: 1.6; SizeY_mm: 0.8; EIA_Code: E96; U/M: EA; AEC Category: Q200; Green_Lifecycle: Active; Green_REACh: Passed
R6 R7 R61 R71 = PE1206FRF470R007L: RES, 0.007, 1%, 1 W, AEC-Q200 Grade 0, 1206; Manufacturer: Yageo America; CompType: Resistor; Value: 0.007; Value_Code: 7L000; Tolerance_%: 1; Value2: 1W; TempCo: 100 ppm/C; SizeArea_mm2: 5.12; SizeX_mm: 3.2; SizeY_mm: 1.6; SizeZ_mm: 0.89; EIA_Code: E96; U/M: EA; AEC Category: Q200; AEC Qualified: Y; AEC Grade: 0
R8 R9 = CRCW060315K0FKEA: RES, 15.0 k, 1%, 0.1 W, 0603; Manufacturer: Vishay-Dale; CompType: Resistor; Value: 15.0k; Res_ohm: 15000; Value_Code: 15k0; Tolerance_%: 1; Power_W: 0.1; Value2: 0.1W; VDC_V: 75; TempCo: 100 ppm/C; SizeArea_mm2: 1.28; SizeX_mm: 1.6; SizeY_mm: 0.8; EIA_Code: E96; U/M: EA; AEC Category: Q200; Green_Lifecycle: Active; Green_REACh: Passed
R10 R13 = CMP-0025697-4: RES, 0, 5%, 0.1 W, AEC-Q200 Grade 0, 0603; Manufacturer: Vishay-Dale; Power_W: 100mW; TempCo: 200 ppm/C; Value_Code: 0000; Value: 0; EIA_Code: E24; SizeX_mm: 1.6; SizeY_mm: 0.8; SizeZ_mm: 1; Value2: 0.1W; SizeArea_mm2: 1.28; CompType: Resistor; AEC Qualified: Y; VDC_V: 75V; AEC Category: Q200
R11 R12 = CMP-0022448-4: RES, 49.9, 1%, 0.1 W, AEC-Q200 Grade 0, 0603; Manufacturer: Vishay-Dale; Power_W: 100mW; TempCo: 100 ppm/C; Value_Code: 49R9; Value: 49.9; EIA_Code: E96; SizeX_mm: 1.6; SizeY_mm: 0.8; SizeZ_mm: 1; Value2: 0.1W; SizeArea_mm2: 1.28; CompType: Resistor; AEC Qualified: Y; VDC_V: 75V; AEC Category: Q200; AEC Grade: 0
R14-R17 = CRCW0603100RFKEA: RES, 100, 1%, 0.1 W, 0603; Manufacturer: Vishay-Dale; CompType: Resistor; Value: 100; Value_Code: 100R; Tolerance_%: 1; Power_W: 0.1; Value2: 0.1W; VDC_V: 75; TempCo: 100 ppm/C; SizeArea_mm2: 1.28; SizeX_mm: 1.6; SizeY_mm: 0.8; EIA_Code: E96; U/M: EA; AEC Category: Q200; Green_Lifecycle: Active; Green_REACh: Passed
R18 R19 = CRCW12064R70JNEAHP: RES, 4.7, 5%, 0.75 W, AEC-Q200 Grade 0, 1206; Manufacturer: Vishay-Dale; CompType: Resistor; Value: 4.7; Value_Code: 4R70; Tolerance_%: 5; Power_W: 0.75; Value2: 0.75W; TempCo: 200 ppm/C; SizeArea_mm2: 5.12; SizeX_mm: 3.2; SizeY_mm: 1.6; SizeZ_mm: 1.35; EIA_Code: E24; U/M: EA; AEC Category: Q200; AEC Qualified: Y; AEC Grade: 0
R22 R29 = CRCW06035K49FKEA: RES, 5.49 k, 1%, 0.1 W, 0603; Manufacturer: Vishay-Dale; CompType: Resistor; Value: 5.49k; Res_ohm: 5490; Value_Code: 5k49; Tolerance_%: 1; Power_W: 0.1; Value2: 0.1W; VDC_V: 75; TempCo: 100 ppm/C; SizeArea_mm2: 1.28; SizeX_mm: 1.6; SizeY_mm: 0.8; EIA_Code: E96; U/M: EA; AEC Category: Q200; Green_Lifecycle: Active; Green_REACh: Passed
R23 = CRCW060349R9FKEA: RES, 49.9, 1%, 0.1 W, 0603; Manufacturer: Vishay-Dale; CompType: Resistor; Value: 49.9; Value_Code: 49R9; Tolerance_%: 1; Power_W: 0.1; Value2: 0.1W; VDC_V: 75; TempCo: 100 ppm/C; SizeArea_mm2: 1.28; SizeX_mm: 1.6; SizeY_mm: 0.8; EIA_Code: E96; U/M: EA; AEC Category: Q200; Green_Lifecycle: Active; Green_REACh: Passed
R26 = CRCW0603221KFKEA: RES, 221 k, 1%, 0.1 W, 0603; Manufacturer: Vishay-Dale; CompType: Resistor; Value: 221k; Res_ohm: 221000; Tolerance_%: 1; Power_W: 0.1; Value2: 0.1W; VDC_V: 75; TempCo: 100 ppm/C; SizeArea_mm2: 1.28; SizeX_mm: 1.6; SizeY_mm: 0.8; EIA_Code: E96; U/M: EA; AEC Category: Q200
R27 = CRCW0603121KFKEA: RES, 121 k, 1%, 0.1 W, 0603; Manufacturer: Vishay-Dale; CompType: Resistor; Value: 121k; Res_ohm: 121000; Tolerance_%: 1; Power_W: 0.1; Value2: 0.1W; VDC_V: 75; TempCo: 100 ppm/C; SizeArea_mm2: 1.28; SizeX_mm: 1.6; SizeY_mm: 0.8; EIA_Code: E96; U/M: EA; AEC Category: Q200; Green_Lifecycle: Active; Green_REACh: Passed
R28 = CRCW060333K2FKEA: RES, 33.2 k, 1%, 0.1 W, 0603; Manufacturer: Vishay-Dale; CompType: Resistor; Value: 33.2k; Res_ohm: 33200; Value_Code: 33k2; Tolerance_%: 1; Power_W: 0.1; Value2: 0.1W; VDC_V: 75; TempCo: 100 ppm/C; SizeArea_mm2: 1.28; SizeX_mm: 1.6; SizeY_mm: 0.8; EIA_Code: E96; U/M: EA; AEC Category: Q200; Green_Lifecycle: Active; Green_REACh: Passed
R30 = CRCW0603110KFKEA: RES, 110 k, 1%, 0.1 W, 0603; Manufacturer: Vishay-Dale; CompType: Resistor; Value: 110k; Res_ohm: 110000; Tolerance_%: 1; Power_W: 0.1; Value2: 0.1W; VDC_V: 75; TempCo: 100 ppm/C; SizeArea_mm2: 1.28; SizeX_mm: 1.6; SizeY_mm: 0.8; EIA_Code: E96; U/M: EA; AEC Category: Q200; Green_Lifecycle: Active; Green_REACh: Passed
R31 = CRCW060318K2FKEA: RES, 18.2 k, 1%, 0.1 W, 0603; Manufacturer: Vishay-Dale; CompType: Resistor; Value: 18.2k; Res_ohm: 18200; Value_Code: 18k2; Tolerance_%: 1; Power_W: 0.1; Value2: 0.1W; VDC_V: 75; TempCo: 100 ppm/C; SizeArea_mm2: 1.28; SizeX_mm: 1.6; SizeY_mm: 0.8; EIA_Code: E96; U/M: EA; AEC Category: Q200; Green_Lifecycle: Active; Green_REACh: Passed
TP1 TP4 = CMP-0055147-2: Test Point, Multipurpose, Red, TH; Manufacturer: Keystone Electronics; CT: TRUE; ContactFinish: Silver; Green_Lifecycle: Active; CNHeader: FALSE; Green_REACh: Passed
TP3 TP5 = CMP-0055148-2: Test Point, Multipurpose, Black, TH; Manufacturer: Keystone Electronics; CNHeader: FALSE; ContactFinish: Silver; Green_REACh: Passed; Green_Lifecycle: Active; CT: TRUE
U1 = CMP-0094639-1: Automotive 3.5-V to 65-V Dual Synchronous Buck Controller With Low IQ; Manufacturer: Texas Instruments; TaMin_C: -40°C; SizeZ_mm: 1mm; Switching Frequency: 0.1-2.2MHz; Standoff Height: 0mm; Number Of Outputs: 2; AEC Grade: Grade 1; Output Type: Fixed,AdjustableProgrammable; TJmax_C: +150°C; Min Supply Voltage: 3.5V; AEC Qualified: Yes; Nominal Supply Current: 15-25uA; TaMax_C: +125°C; Output Voltage: 0.6-55V; Max Supply Voltage: 65V

## Sheet PMP31210RevB-SH2.SchDoc: LM5143 4-Phase Buck 690W
size 431 x 279 mm; Date: Not shown in title block; ApprovedBy: Not shown in title block; CheckedBy: Not shown in title block; Author: Not shown in title block; CompanyName: Not shown in title block; DrawnBy: B. Geck; Engineer: Not shown in title block; Organization: Not shown in title block; Address1: Not shown in title block; Address2: Not shown in title block; Address3: Not shown in title block; Address4: Not shown in title block; DocumentNumber: 2; Revision: Use project parameter SCH_Rev; SheetNumber: 2; SheetTotal: 2; PageSetup: Record=PageOptions¦CenterHorizontal=True¦CenterVertical=True¦PrintScale=0.96¦XCorrection=1.00¦YCorrection=1.00¦PrintKind=0¦BorderSize=5000000¦LeftOffset=0¦BottomOffset=0¦Orientation=2¦PaperLength=1000¦PaperWidth=1000¦Scale=100¦PaperSource=7¦PrintQuality=600¦MediaType=1¦DitherType=10¦PaperKind=11" x 17"¦PrintScaleMode=1
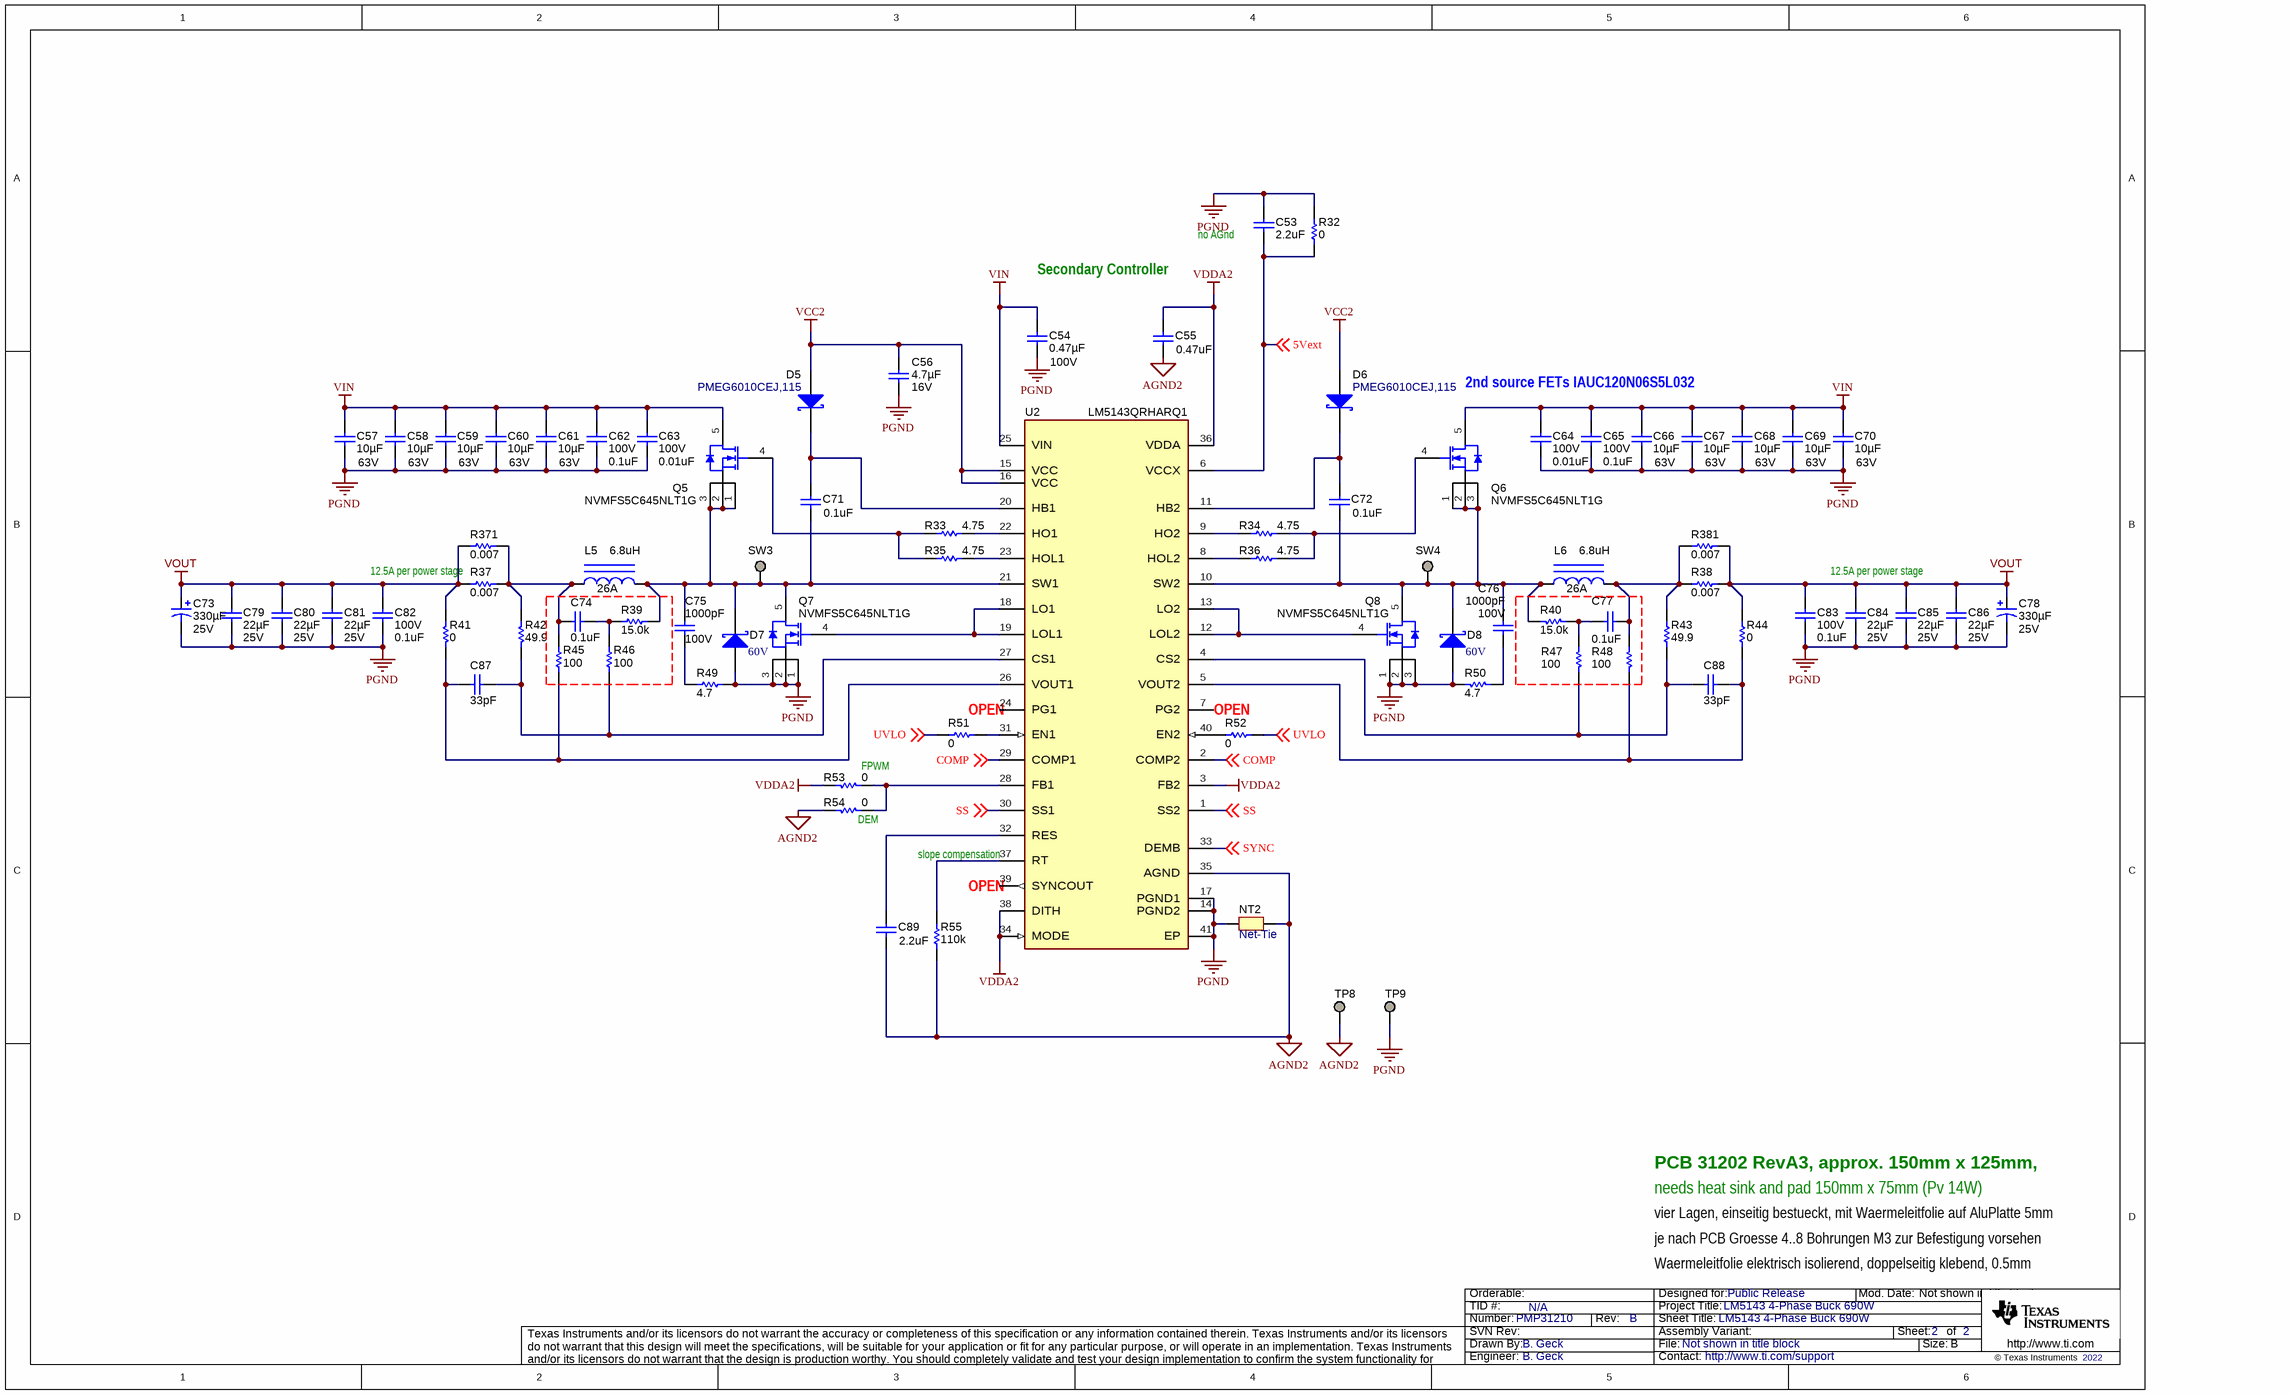
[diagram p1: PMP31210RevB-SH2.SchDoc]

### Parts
C53  ValueDisplayed: 2.2uF  [0603L]  (hidden comment: GRM188R71A225KE15D)
C54  ValueDisplayed: 0.47µF  Value2: 100V  [0805_HV]  (hidden comment: GRM21BR72A474KA73L)
C55  ValueDisplayed: 0.47uF  [0603L]  (hidden comment: GCM188R71C474KA55D)
C56  ValueDisplayed: 4.7µF  Value2: 16V  [0603]  (hidden comment: GRM188Z71C475KE21D)
C57  ValueDisplayed: 10µF  Value2: 63V  [1210_270]  (hidden comment: GRM32ER71J106KA12L)
C58  ValueDisplayed: 10µF  Value2: 63V  [1210_270]  (hidden comment: GRM32ER71J106KA12L)
C59  ValueDisplayed: 10µF  Value2: 63V  [1210_270]  (hidden comment: GRM32ER71J106KA12L)
C60  ValueDisplayed: 10µF  Value2: 63V  [1210_270]  (hidden comment: GRM32ER71J106KA12L)
C61  ValueDisplayed: 10µF  Value2: 63V  [1210_270]  (hidden comment: GRM32ER71J106KA12L)
C62  VDC_V: 100V  ValueDisplayed: 0.1uF  [0805_HV]  (hidden comment: C0805C104K1RACTU)
C63  Value2: 100V  ValueDisplayed: 0.01uF  [0603L]  (hidden comment: GRM188R72A103KA01D)
C64  Value2: 100V  ValueDisplayed: 0.01uF  [0603L]  (hidden comment: GRM188R72A103KA01D)
C65  VDC_V: 100V  ValueDisplayed: 0.1uF  [0805_HV]  (hidden comment: C0805C104K1RACTU)
C66  ValueDisplayed: 10µF  Value2: 63V  [1210_270]  (hidden comment: GRM32ER71J106KA12L)
C67  ValueDisplayed: 10µF  Value2: 63V  [1210_270]  (hidden comment: GRM32ER71J106KA12L)
C68  ValueDisplayed: 10µF  Value2: 63V  [1210_270]  (hidden comment: GRM32ER71J106KA12L)
C69  ValueDisplayed: 10µF  Value2: 63V  [1210_270]  (hidden comment: GRM32ER71J106KA12L)
C70  ValueDisplayed: 10µF  Value2: 63V  [1210_270]  (hidden comment: GRM32ER71J106KA12L)
C71  ValueDisplayed: 0.1uF  [0603L]  (hidden comment: CGA3E2X7R1E104K080AA)
C72  ValueDisplayed: 0.1uF  [0603L]  (hidden comment: CGA3E2X7R1E104K080AA)
C73  ValueDisplayed: 330µF  Value2: 25V  [SM_RADIAL_10BMM]  (hidden comment: EEHZC1E331P)
C74  ValueDisplayed: 0.1uF  [0603L]  (hidden comment: CGA3E2X7R1E104K080AA)
C75  ValueDisplayed: 1000pF  Value2: 100V  [0603]  (hidden comment: GRM188R72A102KA01D)
C76  ValueDisplayed: 1000pF  Value2: 100V  [0603]  (hidden comment: GRM188R72A102KA01D)
C77  ValueDisplayed: 0.1uF  [0603L]  (hidden comment: CGA3E2X7R1E104K080AA)
C78  ValueDisplayed: 330µF  Value2: 25V  [SM_RADIAL_10BMM]  (hidden comment: EEHZC1E331P)
C79  ValueDisplayed: 22µF  Value2: 25V  [1210_270]  (hidden comment: GRM32ER71E226KE15L)
C80  ValueDisplayed: 22µF  Value2: 25V  [1210_270]  (hidden comment: GRM32ER71E226KE15L)
C81  ValueDisplayed: 22µF  Value2: 25V  [1210_270]  (hidden comment: GRM32ER71E226KE15L)
C82  VDC_V: 100V  ValueDisplayed: 0.1uF  [0805_HV]  (hidden comment: C0805C104K1RACTU)
C83  VDC_V: 100V  ValueDisplayed: 0.1uF  [0805_HV]  (hidden comment: C0805C104K1RACTU)
C84  ValueDisplayed: 22µF  Value2: 25V  [1210_270]  (hidden comment: GRM32ER71E226KE15L)
C85  ValueDisplayed: 22µF  Value2: 25V  [1210_270]  (hidden comment: GRM32ER71E226KE15L)
C86  ValueDisplayed: 22µF  Value2: 25V  [1210_270]  (hidden comment: GRM32ER71E226KE15L)
C87  ValueDisplayed: 33pF  [0603L]  (hidden comment: 06031A330JAT2A)
C88  ValueDisplayed: 33pF  [0603L]  (hidden comment: 06031A330JAT2A)
C89  ValueDisplayed: 2.2uF  [0603L]  (hidden comment: GRM188R71A225KE15D)
D5  PMEG6010CEJ,115  [SOD-323F]
D6  PMEG6010CEJ,115  [SOD-323F]
D7  value 60V  [SMA]  (hidden comment: B360A-13-F)
D8  value 60V  [SMA]  (hidden comment: B360A-13-F)
L5  Imax_A: 26A  ValueDisplayed: 6.8uH  [XAL1510]  (hidden comment: XAL1510-682MEB)
L6  Imax_A: 26A  ValueDisplayed: 6.8uH  [XAL1510]  (hidden comment: XAL1510-682MEB)
NT2  Net-Tie  [Net-Tie_10mil]  (net tie, no BOM)
Q5  NVMFS5C645NLT1G  [SO-8FL]
Q6  NVMFS5C645NLT1G  [SO-8FL]
Q7  NVMFS5C645NLT1G  [SO-8FL]
Q8  NVMFS5C645NLT1G  [SO-8FL]
R32  ValueDisplayed: 0  [0603]  (hidden comment: CRCW06030000Z0EA)
R33  ValueDisplayed: 4.75  [0603]  (hidden comment: CRCW06034R75FKEA)
R34  ValueDisplayed: 4.75  [0603]  (hidden comment: CRCW06034R75FKEA)
R35  ValueDisplayed: 4.75  [0603]  (hidden comment: CRCW06034R75FKEA)
R36  ValueDisplayed: 4.75  [0603]  (hidden comment: CRCW06034R75FKEA)
R37  ValueDisplayed: 0.007  [PE1206]  (hidden comment: PE1206FRF470R007L)
R38  ValueDisplayed: 0.007  [PE1206]  (hidden comment: PE1206FRF470R007L)
R39  ValueDisplayed: 15.0k  [0603]  (hidden comment: CRCW060315K0FKEA)
R40  ValueDisplayed: 15.0k  [0603]  (hidden comment: CRCW060315K0FKEA)
R41  ValueDisplayed: 0  [0603L]  (hidden comment: CRCW06030000Z0EA)
R42  ValueDisplayed: 49.9  [0603L]  (hidden comment: CRCW060349R9FKEA)
R43  ValueDisplayed: 49.9  [0603L]  (hidden comment: CRCW060349R9FKEA)
R44  ValueDisplayed: 0  [0603L]  (hidden comment: CRCW06030000Z0EA)
R45  ValueDisplayed: 100  [0603]  (hidden comment: CRCW0603100RFKEA)
R46  ValueDisplayed: 100  [0603]  (hidden comment: CRCW0603100RFKEA)
R47  ValueDisplayed: 100  [0603]  (hidden comment: CRCW0603100RFKEA)
R48  ValueDisplayed: 100  [0603]  (hidden comment: CRCW0603100RFKEA)
R49  ValueDisplayed: 4.7  [1206]  (hidden comment: CRCW12064R70JNEAHP)
R50  ValueDisplayed: 4.7  [1206]  (hidden comment: CRCW12064R70JNEAHP)
R51  ValueDisplayed: 0  [0603]  (hidden comment: CRCW06030000Z0EA)
R52  ValueDisplayed: 0  [0603]  (hidden comment: CRCW06030000Z0EA)
R53  ValueDisplayed: 0  [0603]  (hidden comment: CRCW06030000Z0EA)
R54  ValueDisplayed: 0  [0603]  (hidden comment: CRCW06030000Z0EA)
R55  ValueDisplayed: 110k  [0603]  (hidden comment: CRCW0603110KFKEA)
R371  ValueDisplayed: 0.007  [PE1206]  (hidden comment: PE1206FRF470R007L)
R381  ValueDisplayed: 0.007  [PE1206]  (hidden comment: PE1206FRF470R007L)
SW3  5019  [Keystone_5019]  (value not drawn)
SW4  5019  [Keystone_5019]  (value not drawn)
TP8  5019  [Keystone_5019]  (value not drawn)
TP9  5019  [Keystone_5019]  (value not drawn)
U2  LM5143QRHARQ1  [RHA0040N-MFG]

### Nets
AGND2: C55.1 C89.2 NT2.2 R54.2 R55.1 TP8.1 U2.35(AGND)
PGND: C53.2 C54.2 C56.2 C57.2 C58.2 C59.2 C60.2 C61.2 C62.1 C63.1 C64.1 C65.1 C66.2 C67.2 C68.2 C69.2 C70.2 C73.2(-) C78.2(-) C79.2 C80.2 C81.2 C82.1 C83.1 C84.2 C85.2 C86.2 D7.2(A) D8.2(A) NT2.1 Q7.1(S) Q7.2(S) Q7.3(S) Q8.1(S) Q8.2(S) Q8.3(S) R32.1 R49.1 R50.2 TP9.1 U2.14(PGND2) U2.17(PGND1) U2.41(EP)
VCC2: C56.1 D5.2(A) D6.2(A) U2.15(VCC) U2.16(VCC)
VDDA2: C55.2 R53.2 U2.3(FB2) U2.34(MODE) U2.36(VDDA) U2.38(DITH)
VIN: C54.1 C57.1 C58.1 C59.1 C60.1 C61.1 C62.2 C63.2 C64.2 C65.2 C66.1 C67.1 C68.1 C69.1 C70.1 Q5.5(D) Q6.5(D) U2.25(VIN)
VOUT: C73.1(+) C78.1(+) C79.1 C80.1 C81.1 C82.2 C83.2 C84.1 C85.1 C86.1 R37.1 R38.2 R41.2 R44.2 R371.1 R381.2
5Vext: C53.1 R32.2 U2.6(VCCX) ; off-sheet 5Vext
COMP: U2.2(COMP2) U2.29(COMP1) ; off-sheet COMP
SS: U2.1(SS2) U2.30(SS1) ; off-sheet SS
SYNC: U2.33(DEMB) ; off-sheet SYNC
UVLO: R51.1 R52.2 ; off-sheet UVLO
NetC71_1: C71.1 C75.1 D7.1(K) L5.2 Q5.1(S) Q5.2(S) Q5.3(S) Q7.5(D) R39.2 SW3.1 U2.21(SW1)
NetC71_2: C71.2 D5.1(K) U2.20(HB1)
NetC72_1: C72.1 C76.1 D8.1(K) L6.2 Q6.1(S) Q6.2(S) Q6.3(S) Q8.5(D) R40.2 SW4.1 U2.10(SW2)
NetC72_2: C72.2 D6.1(K) U2.11(HB2)
NetC74_1: C74.1 R39.1 R46.2
NetC74_2: C74.2 L5.1 R37.2 R42.2 R45.2 R371.2
NetC75_2: C75.2 R49.2
NetC76_2: C76.2 R50.1
NetC77_1: C77.1 R40.1 R47.2
NetC77_2: C77.2 L6.1 R38.1 R43.2 R48.2 R381.1
NetC87_1: C87.1 R41.1 R45.1 U2.26(VOUT1)
NetC87_2: C87.2 R42.1 R46.1 U2.27(CS1)
NetC88_1: C88.1 R44.1 R48.1 U2.5(VOUT2)
NetC88_2: C88.2 R43.1 R47.1 U2.4(CS2)
NetC89_1: C89.1 U2.32(RES)
NetQ5_4: Q5.4(G) R33.1 R35.1
NetQ6_4: Q6.4(G) R34.2 R36.2
NetQ7_4: Q7.4(G) U2.18(LO1) U2.19(LOL1)
NetQ8_4: Q8.4(G) U2.12(LOL2) U2.13(LO2)
NetR33_2: R33.2 U2.22(HO1)
NetR34_1: R34.1 U2.9(HO2)
NetR35_2: R35.2 U2.23(HOL1)
NetR36_1: R36.1 U2.8(HOL2)
NetR51_2: R51.2 U2.31(EN1)
NetR52_1: R52.1 U2.40(EN2)
NetR53_1: R53.1 R54.1 U2.28(FB1)
NetR55_2: R55.2 U2.37(RT)

Not connected (* = marked no-connect by the designer): U2 7(PG2) 24(PG1) 39(SYNCOUT)

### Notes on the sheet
- Secondary Controller
- (near C53) no AGnd
- 2nd source FETs IAUC120N06S5L032
- (near R37) 12.5A per power stage
- (near R38) 12.5A per power stage
- OPEN
- (near R53) FPWM
- (near R54) DEM
- (near U2) slope compensation
- (near U2) OPEN
- PCB 31202 RevA3, approx. 150mm x 125mm,
- vier Lagen, einseitig bestueckt, mit Waermeleitfolie auf AluPlatte 5mm
- needs heat sink and pad 150mm x 75mm (Pv 14W)
- je nach PCB Groesse 4..8 Bohrungen M3 zur Befestigung vorsehen
- Waermeleitfolie elektrisch isolierend, doppelseitig klebend, 0.5mm

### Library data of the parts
C53 = CMP-0007370-4: as C11 on sheet PMP31210RevB-SH1
C54 = GRM21BR72A474KA73L: as C12 on sheet PMP31210RevB-SH1
C55 = CMP-0007138-4: as C13 on sheet PMP31210RevB-SH1
C56 = GRM188Z71C475KE21D: as C14 on sheet PMP31210RevB-SH1
C57-C61 C66-C70 = GRM32ER71J106KA12L: as C1 on sheet PMP31210RevB-SH1
C62 C65 C82 C83 = CMP-0007722-2: as C2 on sheet PMP31210RevB-SH1
C63 C64 = CMP-0007468-5: as C3 on sheet PMP31210RevB-SH1
C71 C72 C74 C77 = CMP-0007077-5: as C29 on sheet PMP31210RevB-SH1
C73 C78 = EEHZC1E331P: as C35 on sheet PMP31210RevB-SH1
C75 C76 = GRM188R72A102KA01D: as C32 on sheet PMP31210RevB-SH1
C79-C81 C84-C86 = GRM32ER71E226KE15L: as C37 on sheet PMP31210RevB-SH1
C87 C88 = CMP-0006722-4: as C45 on sheet PMP31210RevB-SH1
C89 = CMP-0007370-4: as C50 on sheet PMP31210RevB-SH1
D5 D6 = CMP-0077011-2: as D1 on sheet PMP31210RevB-SH1
D7 D8 = B360A-13-F: as D3 on sheet PMP31210RevB-SH1
L5 L6 = CMP-0060971-1: as L3 on sheet PMP31210RevB-SH1
NT2 = CMP-0078142-3: Single point connection between nets.
Q5-Q8 = NVMFS5C682NLT1G: as Q1 on sheet PMP31210RevB-SH1
R32 R51-R54 = CRCW06030000Z0EA: as R1 on sheet PMP31210RevB-SH1
R33-R36 = CRCW06034R75FKEA: as R2 on sheet PMP31210RevB-SH1
R37 R38 R371 R381 = PE1206FRF470R007L: as R6 on sheet PMP31210RevB-SH1
R39 R40 = CRCW060315K0FKEA: as R8 on sheet PMP31210RevB-SH1
R41 R44 = CMP-0025697-4: as R10 on sheet PMP31210RevB-SH1
R42 R43 = CMP-0022448-4: as R11 on sheet PMP31210RevB-SH1
R45-R48 = CRCW0603100RFKEA: as R14 on sheet PMP31210RevB-SH1
R49 R50 = CRCW12064R70JNEAHP: as R18 on sheet PMP31210RevB-SH1
R55 = CRCW0603110KFKEA: as R30 on sheet PMP31210RevB-SH1
SW3 SW4 TP8 TP9 = CMP-0055162-1: as NWA on sheet PMP31210RevB-SH1
U2 = CMP-0094639-1: as U1 on sheet PMP31210RevB-SH1

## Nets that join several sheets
PGND: PMP31210RevB-SH1 (61 pins), PMP31210RevB-SH2 (43 pins)
VIN: PMP31210RevB-SH1 (24 pins), PMP31210RevB-SH2 (18 pins)
VOUT: PMP31210RevB-SH1 (19 pins), PMP31210RevB-SH2 (16 pins)
5Vext: PMP31210RevB-SH1 (C11.1 J2.2 R1.2 U1.6), PMP31210RevB-SH2 (C53.1 R32.2 U2.6)
COMP: PMP31210RevB-SH1 (C47.1 R28.2 U1.2 U1.29), PMP31210RevB-SH2 (U2.2 U2.29)
SS: PMP31210RevB-SH1 (C49.1 U1.1 U1.30), PMP31210RevB-SH2 (U2.1 U2.30)
SYNC: PMP31210RevB-SH1 (U1.39), PMP31210RevB-SH2 (U2.33)
UVLO: PMP31210RevB-SH1 (6 pins), PMP31210RevB-SH2 (R51.1 R52.2)

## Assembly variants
built: not fitted C11 C31 C32 C33 C34 C53 C74 C75 C76 C77 R8 R9 R14 R15 R16 R17 R18 R19 R25 R39 R40 R45 R46 R47 R48 R49 R50 R54; alternate parts R22 -> CRCW06030000Z0EA
with IHLP footprint: alternate parts L3 -> CMP-0063534-2, L4 -> CMP-0063534-2, L5 -> CMP-0063534-2, L6 -> CMP-0063534-2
